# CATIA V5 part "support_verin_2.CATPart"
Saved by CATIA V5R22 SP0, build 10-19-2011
Part number: Support bloc boite
Bounding box of the stored display mesh (mm): x -140 to 140, y -350 to 290, z 0 to 5
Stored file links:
  D:\PER\CAO_PER_MODIF_2025\CAO_PER_pick&place_2024P\Sous_Ensemble_Boite\Support bloc boite.CATPart
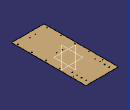
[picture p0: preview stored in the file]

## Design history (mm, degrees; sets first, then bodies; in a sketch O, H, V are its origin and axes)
Body1 (main body)
  Sketch1 on xy-plane, origin (0, 0, 0), H (1, 0, 0), V (0, 1, 0)
    line L1 (140, 350) -> (140, -350)
    line L2 (140, -350) -> (-140, -350)
    line L3 (-140, -350) -> (-140, 350)
    line L4 (-140, 350) -> (140, 350)
    length L1 = 700
    length L4 = 280
    vertical: L1 V, L3 V
    horizontal: L2 H, L4 H
    equidistance: L1 L3 O, L2 L4 O
  Pad1: profile Sketch1, direction (0, 0, 1), length 5
  Sketch2 on end face of Pad1, origin (0, 0, 5), H (1, 0, 0), V (0, 1, 0)
    projected line E1 (140, 350) -> (-140, 350) from edge [face of Pad1 from Sketch1.L4 | end face of Pad1]
    line L1 (140, 350) -> (140, 290)
    line L2 (140, 290) -> (-140, 290)
    line L3 (-140, 290) -> (-140, 350)
    distance L2 E1 = 60
    vertical: L1 V, L3 V
    horizontal: L2 H
  Pocket1: profile Sketch2, direction (0, 0, -1), through (limit type 3)
  DatumCurve1 to DatumCurve12
  Sketch3 on end face of Pad1, origin (0, 0, 5), H (1, 0, 0), V (0, 1, 0)
    projected circle E1 centre (99, 132.4085) radius 3.25 from edge of DatumCurve1
    projected circle E2 centre (99, 172.4085) radius 3.25 from edge of DatumCurve2
    projected circle E3 centre (99, 212.4085) radius 3.25 from edge of DatumCurve3
    projected circle E4 centre (99, 252.4085) radius 3.25 from edge of DatumCurve4
    projected circle E5 centre (-99, 252.4085) radius 3.25 from edge of DatumCurve5
    projected circle E6 centre (-99, 212.4085) radius 3.25 from edge of DatumCurve6
    projected circle E7 centre (-99, 172.4085) radius 3.25 from edge of DatumCurve7
    projected circle E8 centre (-99, 132.4085) radius 3.25 from edge of DatumCurve8
    projected circle E9 centre (22.5, -77.9975) radius 2.5 from edge of DatumCurve9
    projected circle E10 centre (-24.5, -77.9975) radius 2.5 from edge of DatumCurve10
    projected circle E11 centre (23, -308.9975) radius 2.5 from edge of DatumCurve11
    projected circle E12 centre (-24, -308.9975) radius 2.5 from edge of DatumCurve12
  Pocket2: profile Sketch3, direction (0, 0, -1), through (limit type 3)
  Chamfer1: length 4, angle 45, on edge [face of Pocket2 from Sketch3.E5 | start face of Pad1]; edge [face of Pocket2 from Sketch3.E6 | start face of Pad1]; edge [face of Pocket2 from Sketch3.E7 | start face of Pad1]; start face of Pad1; edge [face of Pocket2 from Sketch3.E4 | start face of Pad1]; edge [face of Pocket2 from Sketch3.E3 | start face of Pad1]; edge [face of Pocket2 from Sketch3.E2 | start face of Pad1]; edge [face of Pocket2 from Sketch3.E1 | start face of Pad1]
  Sketch4 on end face of Pad1, origin (0, 0, 5), H (1, 0, 0), V (0, 1, 0)
    circle A1 centre (125, -310) radius 3.5
    point P1 (125, -310)
    reference projected line E1 (-140, -350) -> (140, -350) from edge [face of Pad1 from Sketch1.L2 | end face of Pad1]
    reference projected line E2 (140, -350) -> (140, 350) from edge [face of Pad1 from Sketch1.L1 | end face of Pad1]
    reference intersected line E3 through (0, 0) direction (0, 1) from yz-plane
    circle A2 centre (-125, -310) radius 3.5
    distance P1 E1 = 40
    radius A1 = 3.5
    distance E2 P1 = 15
    symmetry: A1 A2 E3
  Pocket3: profile Sketch4, direction (0, 0, -1), through (limit type 3)
  RectPattern1: of Pocket3, direction 1 instances 5, spacing 120, along edge [face of Pad1 from Sketch1.L1 | end face of Pad1]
